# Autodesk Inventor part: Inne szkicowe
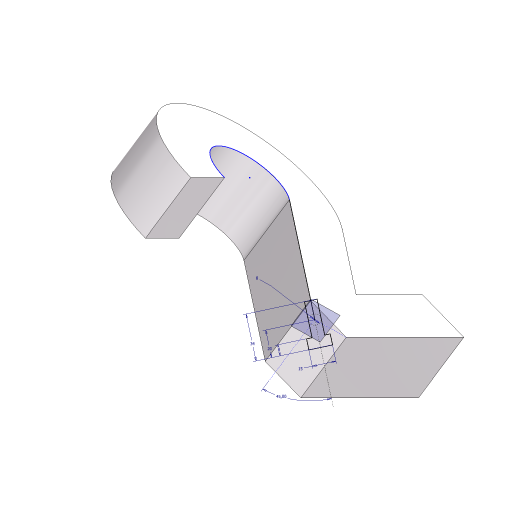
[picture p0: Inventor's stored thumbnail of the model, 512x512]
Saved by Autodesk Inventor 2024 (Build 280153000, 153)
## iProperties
Company: ATC
Created: 2023-03
Part Number: Inne szkicowe
Document SubType Name: Modeling
Designer: Andrzej Jaskulski
Manufacturer: Standard
Standards Organization: Custom
Material: Kurs-AJ
Density: 1 g/cm^3
Mass: 879.444 g
Surface Area: 822.452 cm^2
Volume: 879.444 cm^3
Appearance: Kurs-AJ
Checked By: A.J.
Engr Approved By: Andrzej Jaskulski
Mfg Approved By: Andrzej Jaskulski
Authority: A.J.
Title: A.J.: Kurs R2024-MEP
Author: Andrzej Jaskulski
Revision Number: 1/24
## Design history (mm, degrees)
sketch "Zarys dwójki"
  geometry: L1 (0, 0)-(140, 0); L2 (140, 0)-(140, 40); L3 (140, 40)-(61.086, 40); L4 (0, 0)-(0, 34.326); L5 (0, 34.326)-(91.58, 129.16); L6 (61.086, 40)-(120.354, 101.374); L7 (40, 150)-(0, 150); A1 r 30 centre (70, 150) between (91.58, 129.16) and (40, 150); A2 r 70 centre (70, 150) between (120.354, 101.374) and (0, 150)
  constraints: 14 end point, 4 point on circle, 3 perpendicular, 2 centre point, 2 parallel, 2 tangent, 1 coincident, 1 horizontal, 1 point on line, 1 other
  dimensions: "d0" = 140 distance of L1.start L1.end; "d1" = 150 distance from line of A1.centre L1; "d2" = 70 radius of A2; "d3" = 30 radius of A1; "d4" = 70 distance from line of L4 A1.centre; "d5" = 46 deg angle of L6 L3; "d6" = 40 distance of L1.end L2.end
extrude "Dwójka" new body sketch "Zarys dwójki" distance "d7" = 50; taper "d8" = 0 deg
node "Prostopadła do Ścieżki"
sketch "Rowek"
  geometry: L1 (0, 0)-(23.845, 0) reference; L2 (23.845, -50)-(23.845, 0) reference; L3 (23.845, 0)-(-20.721, -44.566); L4 (36.573, 7.071)-(18.188, -11.314); L5 (18.188, -11.314)-(20.663, -13.789); L6 (20.663, -13.789)-(15.006, -19.445); L7 (15.006, -19.445)-(4.4, -8.839); L8 (4.4, -8.839)-(10.056, -3.182); L9 (10.056, -3.182)-(12.531, -5.657); L10 (12.531, -5.657)-(30.916, 12.728); L11 (30.916, 12.728)-(36.573, 7.071); C1 r 4 at (23.845, 0)
  constraints: 18 end point, 6 parallel, 2 equal length, 2 tangent, 1 centre point, 1 coincident, 1 collinear, 1 perpendicular
  dimensions: "d23" = 45 deg angle of L3 L2; "d24" = 8 diameter of C1; "d25" = 15 distance of L6.end L7.end; "d26" = 20 distance from line of L1.end L7; "d27" = 34 distance between parallel lines of L7 L11; "d28" = 8 distance of L5.end L6.end
sketch "Ścieżka 2D"
  geometry: L1 (91.58, 129.16)-(-17.153, 16.564); L2 (-14.275, 13.785)-(-20.03, 19.343) reference; A1 r 30 centre (70, 150) between (91.58, 129.16) and (40, 150) reference
  constraints: 2 end point, 1 midpoint, 1 tangent
node "Bryła1"
node "Korpusy bryłowe"
node "Korpusy powierzchniowe"
